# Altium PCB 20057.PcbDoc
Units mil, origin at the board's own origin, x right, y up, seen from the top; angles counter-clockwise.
Board outline 3410.03 x 2160.03 mil, 4 copper layers (Top Layer, Internal Plane 1, Internal Plane 2, Bottom Layer), stack 61.88 mil thick; 85 components, 49 nets, 375 pads, 184 vias.
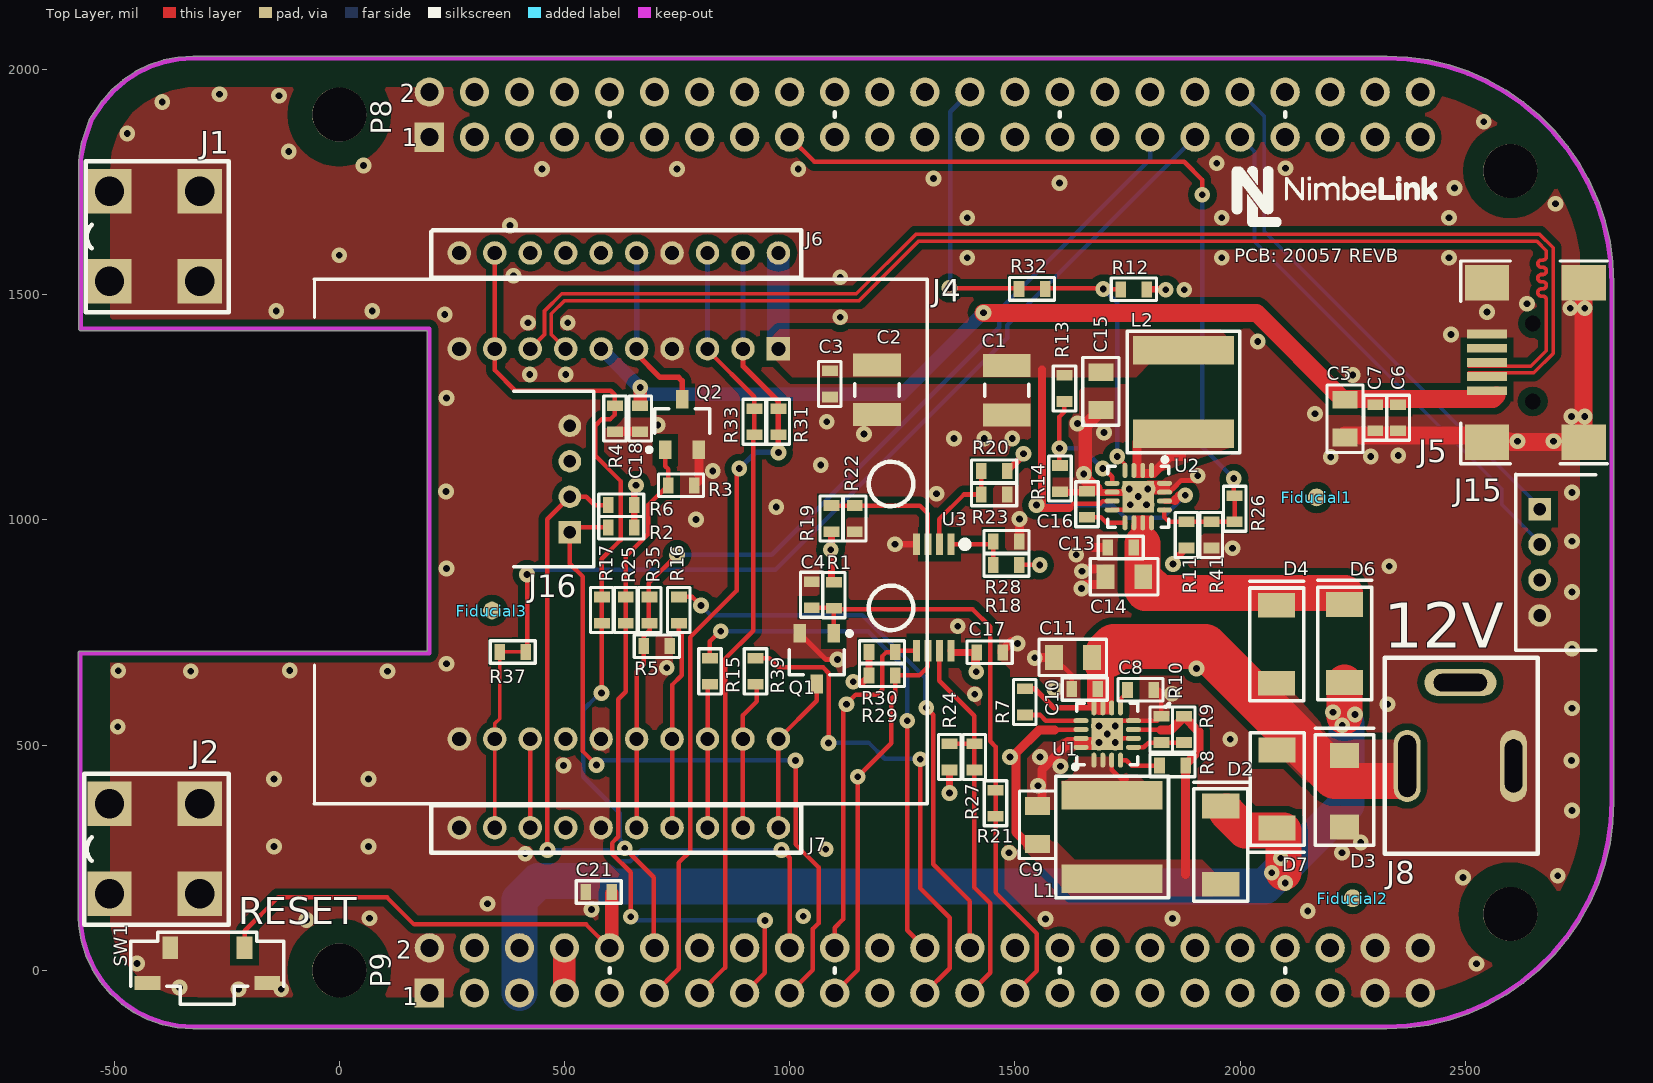
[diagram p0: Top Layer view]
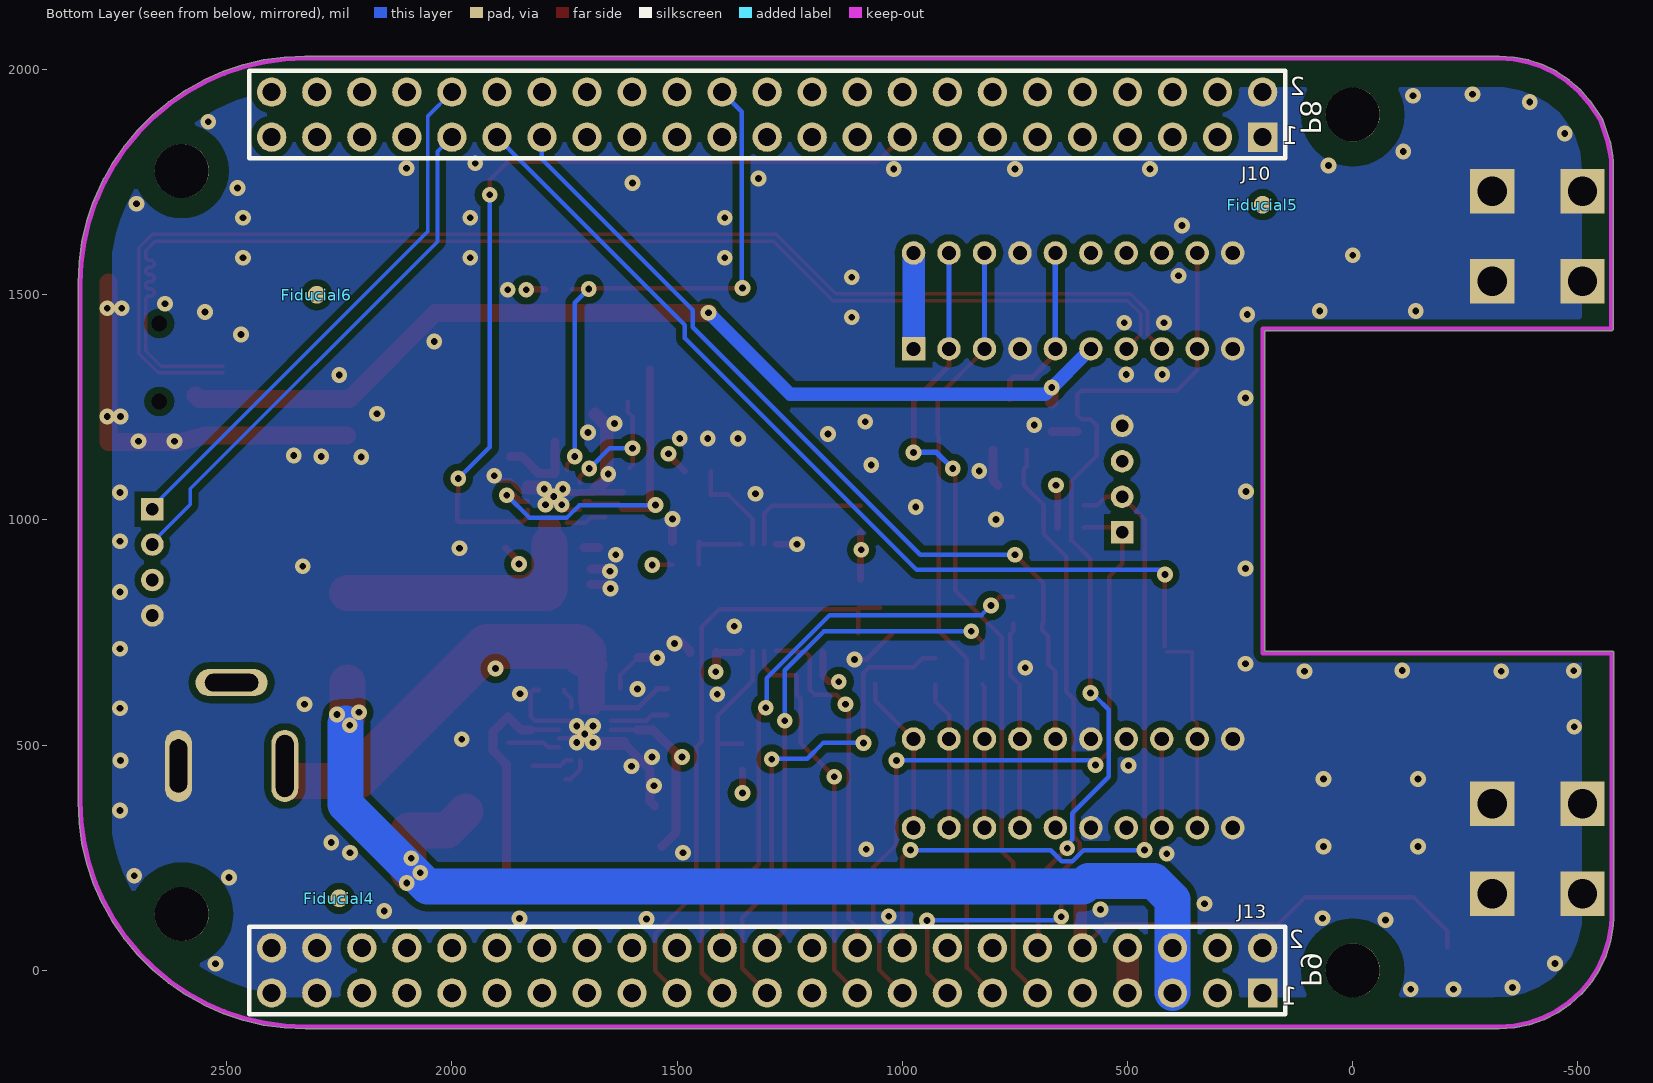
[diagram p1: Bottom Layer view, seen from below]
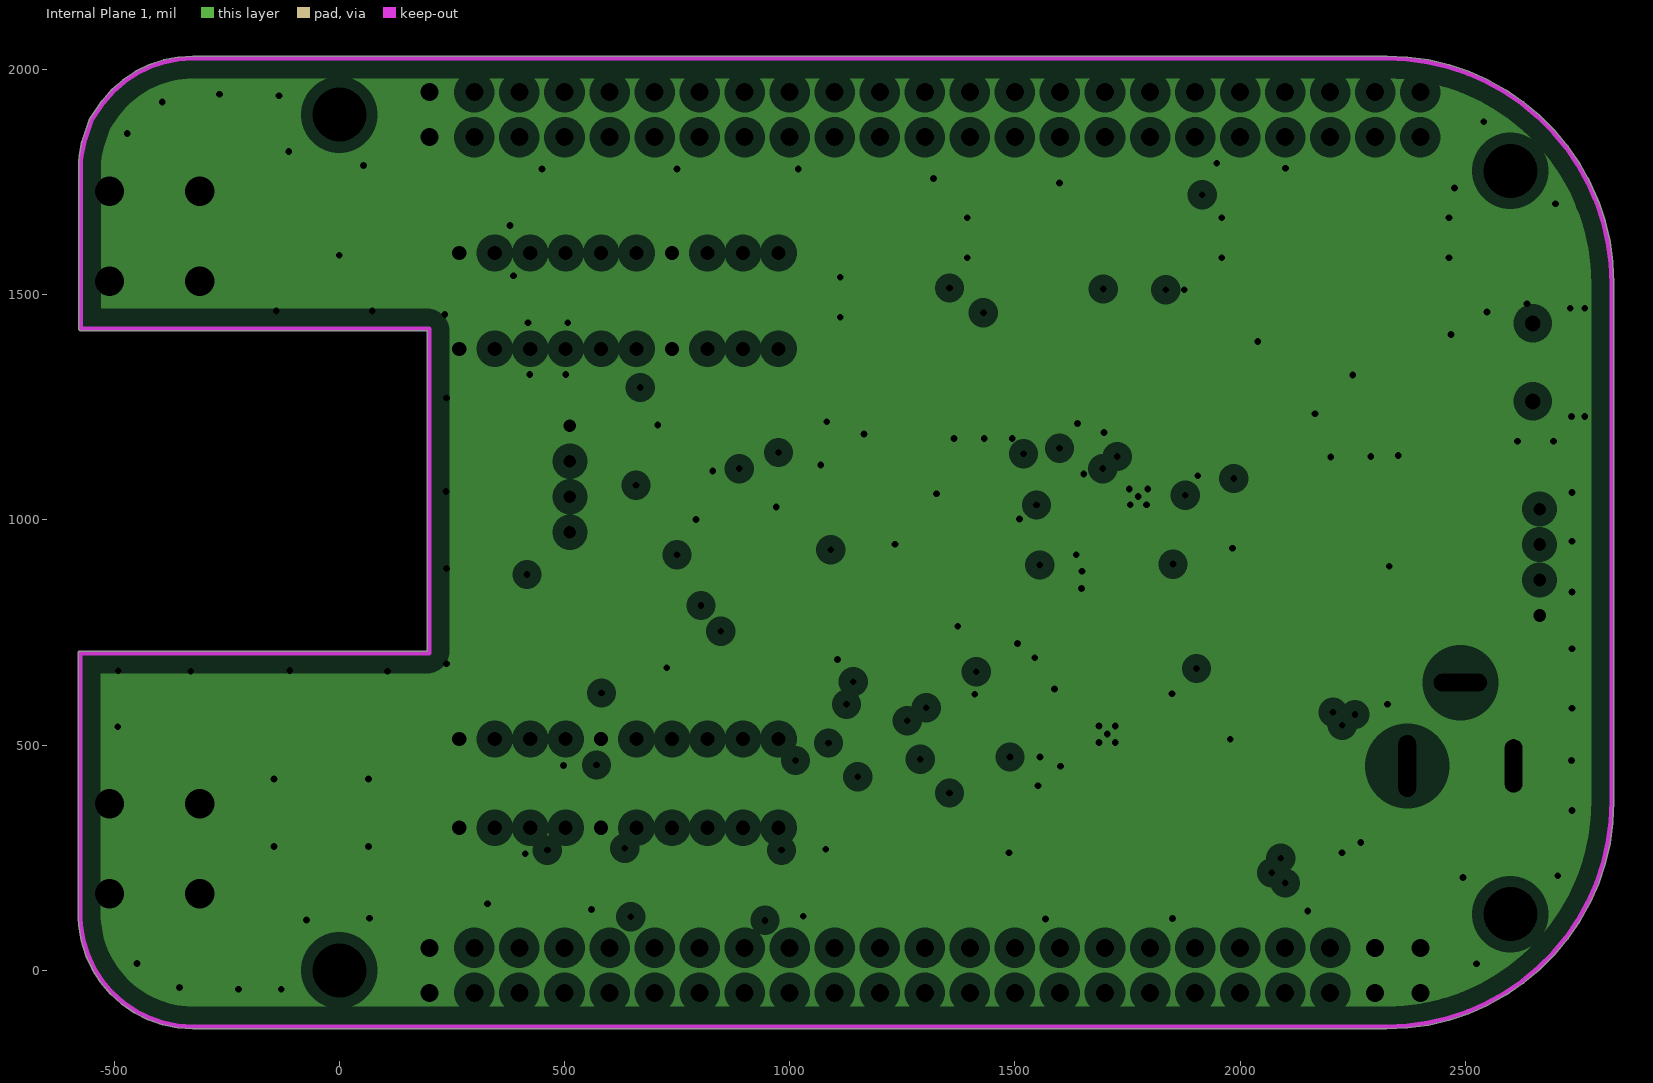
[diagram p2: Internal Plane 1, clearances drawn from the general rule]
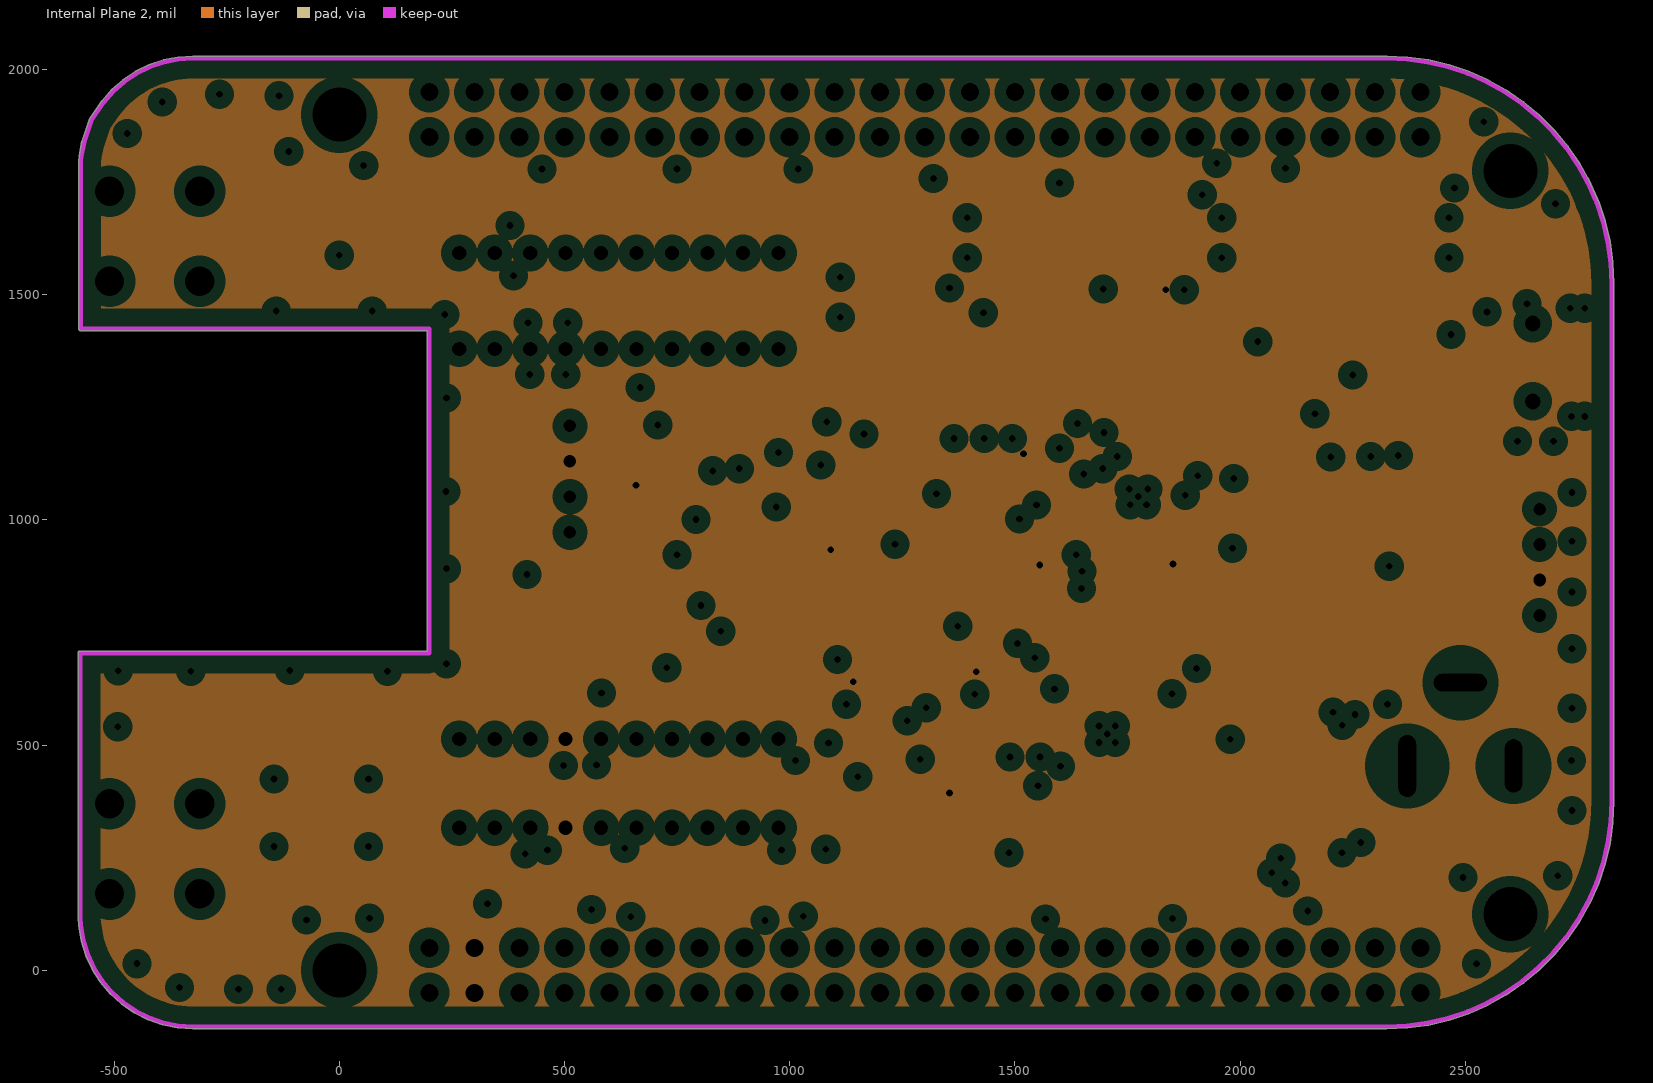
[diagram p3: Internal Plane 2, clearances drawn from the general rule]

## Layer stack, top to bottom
Top Solder: solder mask 0.4, Solder Resist, Dk 3.5
Top Layer: signal copper 1.37
Dielectric 1: core 6.7, FR-4, Dk 4.6
Internal Plane 1: plane copper 1.37, net GND
Dielectric 3: prepreg 43, Dk 4.2
Internal Plane 2: plane copper 1.37, net VCC_3V3
Dielectric 2: core 6.7, Dk 4.2
Bottom Layer: signal copper 1.37
Bottom Solder: solder mask 0.4, Solder Resist, Dk 3.5

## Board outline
-562.85,33.06 cw(c-558.3,35.17) -563.09,33.68 -572.98,65.58 cw(c-568.19,67.07) -573.14,66.25 -578.69,99.15 cw(c-573.75,100) -578.75,99.64 -579.97,116.76 cw(c-574.96,117.11) -579.98,117.11 -580.02,165 cw(c-575,165) -580.02,165 -580.02,328.93 -580.02,445 cw(c-575,445) -580.01,445.06 -580.01,445 ccw(c-575,445) -580.01,445 -580.01,445.06 -580.01,703.84 cw(c-575,703.84) -575,708.86 194.99,708.86 194.98,1419.99 -573.59,1419.98 cw(c-573.59,1425) -578.61,1425 -578.61,1796.44 cw(c-573.59,1796.44) -578.6,1796.77 -577.87,1807.96 cw(c-572.86,1807.63) -577.78,1808.63 -571.4,1840.67 cw(c-566.48,1839.71) -571.23,1841.32 -571.22,1841.34 -555.42,1887.88 cw(c-550.67,1886.29) -554.84,1889.08 -554.83,1889.08 -527.51,1929.97 -527.5,1929.98 ccw(c-523.34,1927.19) -527.51,1929.97 -527.51,1929.98 cw(c-523.34,1927.19) -527.11,1930.5 -505.55,1955.08 cw(c-501.78,1951.78) -505.08,1955.55 -480.5,1977.11 cw(c-477.19,1973.34) -479.98,1977.51 -479.97,1977.51 -452.79,1995.67 cw(c-450,1991.51) -452.78,1995.68 -452.79,1995.68 cw(c-450,1991.51) -452.2,1996.01 -422.91,2010.46 cw(c-420.67,2005.97) -422.28,2010.72 -422.27,2010.72 -391.33,2021.23 cw(c-389.7,2016.48) -390.68,2021.4 -358.61,2027.78 cw(c-357.63,2022.86) -357.96,2027.87 -325.33,2030 cw(c-325,2025) -325,2030.02 2325,2030.02 cw(c2325,2025) 2325.25,2030.01 2371.34,2027.88 cw(c2371.13,2022.87) 2371.83,2027.83 2371.82,2027.83 cw(c2371.13,2022.87) 2371.83,2027.83 2417.56,2021.45 cw(c2416.87,2016.49) 2417.57,2021.45 2417.56,2021.45 2417.57,2021.45 cw(c2416.87,2016.49) 2418.02,2021.37 2462.98,2010.79 cw(c2461.83,2005.91) 2463.44,2010.66 2463.43,2010.67 2463.44,2010.66 2507.2,1996 2507.21,1995.99 2507.2,1996 cw(c2505.62,1991.24) 2507.65,1995.82 2549.89,1977.17 cw(c2547.87,1972.58) 2550.32,1976.96 2590.64,1954.5 cw(c2588.22,1950.11) 2591.05,1954.25 2591.06,1954.24 ccw(c2588.22,1950.11) 2590.66,1954.49 2590.64,1954.5 2591.06,1954.24 2629.14,1928.16 2629.15,1928.15 cw(c2626.32,1924.01) 2629.53,1927.86 2665.04,1898.37 2665.05,1898.36 cw(c2661.85,1894.5) 2665.41,1898.03 2665.39,1898.05 2698.05,1865.39 cw(c2694.5,1861.85) 2698.37,1865.04 2727.86,1829.53 cw(c2724.01,1826.32) 2728.15,1829.15 2728.16,1829.14 2754.24,1791.06 2754.25,1791.05 cw(c2750.11,1788.22) 2754.5,1790.64 2754.49,1790.66 ccw(c2750.11,1788.22) 2754.24,1791.06 2754.5,1790.64 2772.43,1758.45 cw(c2769.9,1754.12) 2774.49,1756.15 2793.14,1713.9 cw(c2788.56,1711.87) 2793.57,1711.87 cw(c2788.56,1711.87) 2793.28,1710.2 cw(c2791.24,1705.62) 2795.99,1707.21 2810.66,1663.44 2810.67,1663.43 2810.66,1663.44 cw(c2805.91,1661.83) 2810.79,1662.98 2821.37,1618.02 cw(c2816.49,1616.87) 2821.45,1617.57 2821.45,1617.56 2827.83,1571.83 cw(c2822.87,1571.13) 2827.83,1571.82 2827.83,1571.83 cw(c2822.87,1571.13) 2827.88,1571.34 2827.88,1571.37 2827.88,1571.34 2830.01,1525.25 cw(c2825,1525) 2830.02,1525 2830.02,375 cw(c2825,375) 2830.01,374.75 2830.01,374.77 2830.01,374.75 2827.88,328.66 2827.88,328.63 2827.88,328.66 cw(c2822.87,328.87) 2827.83,328.17 2827.83,328.18 cw(c2822.87,328.87) 2827.83,328.17 2827.83,328.18 2827.83,328.17 2821.45,282.44 2821.45,282.43 ccw(c2816.49,283.13) 2821.45,282.44 2821.45,282.43 cw(c2816.49,283.13) 2821.37,281.98 2810.79,237.02 cw(c2805.91,238.17) 2810.66,236.56 2810.67,236.57 2810.66,236.56 2796,192.8 2795.99,192.79 2796,192.8 cw(c2791.24,194.38) 2795.82,192.35 2777.17,150.11 cw(c2772.58,152.13) 2776.96,149.68 2776.96,149.69 2776.96,149.68 2754.5,109.36 cw(c2750.11,111.78) 2754.25,108.95 2728.15,70.85 cw(c2724.01,73.68) 2727.86,70.47 2727.87,70.48 2727.86,70.47 2698.37,34.96 2698.36,34.95 2698.37,34.96 cw(c2694.5,38.15) 2698.05,34.61 2665.39,1.95 cw(c2661.85,5.5) 2665.04,1.63 2665.05,1.64 2665.04,1.63 2629.53,-27.86 2629.52,-27.87 cw(c2626.32,-24.01) 2629.14,-28.16 2629.15,-28.15 ccw(c2626.32,-24.01) 2629.53,-27.86 2629.14,-28.16 2591.06,-54.24 2591.05,-54.25 cw(c2588.22,-50.11) 2590.64,-54.5 2590.66,-54.49 ccw(c2588.22,-50.11) 2591.06,-54.24 2590.64,-54.5 2550.32,-76.96 2550.31,-76.96 2550.32,-76.96 cw(c2547.87,-72.58) 2549.89,-77.17 2507.65,-95.82 cw(c2505.62,-91.24) 2507.2,-96 2507.21,-95.99 2507.2,-96 2463.44,-110.66 cw(c2461.83,-105.91) 2462.98,-110.79 2418.02,-121.37 cw(c2416.87,-116.49) 2417.55,-121.46 2417.57,-121.45 2417.55,-121.46 2371.84,-127.83 2371.83,-127.83 cw(c2371.13,-122.87) 2371.34,-127.88 2371.37,-127.88 ccw(c2371.13,-122.87) 2371.84,-127.83 2371.34,-127.88 2325.25,-130.01 2325.23,-130.01 2325.25,-130.01 cw(c2325,-125) 2325,-130.01 -325,-130.01 cw(c-325,-125) -325.34,-130 -358.66,-127.77 cw(c-358.32,-122.77) -359.32,-127.68 -392.05,-121.03 cw(c-391.05,-116.12) -392.7,-120.85 -424.25,-109.9 cw(c-422.6,-105.16) -424.87,-109.64 -454.67,-94.57 cw(c-452.41,-90.1) -455.25,-94.23 -482.78,-75.33 cw(c-479.95,-71.19) -483.31,-74.91 -508.08,-52.51 cw(c-504.72,-48.79) -508.54,-52.03 cw(c-504.72,-48.79) -508.55,-52.02 -530.1,-26.52 -530.11,-26.52 cw(c-526.28,-23.28) -530.5,-25.98 -548.47,2.17 cw(c-544.25,4.87) -548.8,2.76

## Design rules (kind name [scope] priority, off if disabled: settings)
Clearance Clearance_1 [InPolygon] p1: gap=15
Clearance [All] p2: gap=6
ComponentClearance [All] p1: gap=7 collisioncheckmode=3 verticalgap=7 showdistances=FALSE
DiffPairsRouting [All] p1: maxlimit=30 minlimit=7 mostfreqgap=7 toplayer_minwidth=7 toplayer_maxwidth=100 toplayer_prefwidth=8 bottomlayer_minwidth=7 bottomlayer_maxwidth=100 bottomlayer_prefwidth=8 maxuncoupledlength=500
HoleSize [All] p1: absolutevalues=TRUE maxlimit=500 minlimit=15 maxpercent=80.000 minpercent=20.000
MinimumAnnularRing [All] p1: minimumring=10
MinimumSolderMaskSliver [All] p1: minsoldermaskwidth=0
PlaneClearance [All] p1: clearance=25
PlaneConnect [All] p1: planeconnectstyle=Direct reliefexpansion=20 reliefentries=4 reliefconductorwidth=20 reliefairgap=15
PolygonConnect "All Rule" [All] p1: connectstyle=Direct reliefconductorwidth=10 reliefentries=4 polygonreliefangle="90 Angle" airgapwidth=10
RoutingVias [All] p1: holewidth=15 width=35 viastyle="Through Hole" minholewidth=15 minwidth=35 maxholewidth=300 maxwidth=500
ShortCircuit ShortCircuit_1 [(InComponent('J9') OR InComponent('J10') OR InComponent('J11') OR InComponent('J12') OR InComponent('J13') OR InComponent('J14')) vs (InComponent('J9') OR InComponent('J10') OR InComponent('J11') OR InComponent('J12') OR InComponent('J13') OR InComponent('J14'))] p1 off: allowed=TRUE
ShortCircuit [All] p2: allowed=FALSE
SilkToSilkClearance [All] p1: silktosilkclearance=0
SilkToSolderMaskClearance [IsPad] p1: minsilkscreentomaskgap=0 clearancetoexposedcopper=TRUE
SolderMaskExpansion SolderMaskExpansion_2 [isVia and TestpointBottom] p1: expansion=0
SolderMaskExpansion SolderMaskExpansion_1 [IsVia] p2: expansion=-10
SolderMaskExpansion [All] p3: expansion=0
UnpouredPolygon [All] p1: allowunpoured=FALSE
Width [All] p1: maxlimit=5000 minlimit=7 preferedwidth=10
20 further rules are at their usual default settings.

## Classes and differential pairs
component class Skywire: C1 C2 C3 C4 C5 C6 C7 C18 J1 J2 J4 J5 J6 J7 Q1 Q2 R1 R3 R4 R5
net class DIFF90: SKY_USB_N SKY_USB_P
component class Power: C8 C9 C10 C11 C13 C14 C15 C16 D2 D3 D4 D6 D7 J8 L1 L2 R7 R8 R9 R10 R11 R12 R13 R14 R41 U1 U2
component class TOP: C17 C21 Fiducial1 Fiducial2 Fiducial3 Fiducial4 Fiducial5 Fiducial6 J10 J13 J15 J16 R2 R6 R15 R16 R17 R18 R19 R20 R21 R22 R23 R24 R25 R26 R27 R28 R29 R30 R31 R32 R33 R35 R37 R39 SW1 U3
differential pair SKY_USB: +SKY_USB_P -SKY_USB_N

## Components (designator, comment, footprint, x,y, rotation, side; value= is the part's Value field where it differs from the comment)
C1 "LMK325BJ107MM-T" CAPC3225X25N_1210 1482,1288 r270 top
C2 "LMK325BJ107MM-T" CAPC3225X25N_1210 1194,1289 r270 top
C3 "C, 0.1 uF, 16V, 5%, X7R, 0603 CER" 0603 1089,1302 r270 top
C4 "C, 0.1 uF, 16V, 5%, X7R, 0603 CER" 0603 1049,834 r90 top
C5 "C, 10 uF, 25V, 10% ,X5R, 0805 CER" 0805 2233,1216 r270 top
C6 "C, 0.1 uF, 16V, 5%, X7R, 0603 CER" 0603 2351,1227 r270 top
C7 "C, 10 nF, 25V, 10%, X7R, 0603 CER" 0603 2300,1227 r270 top
C8 "C, 470 pF, 50V, NP0, 0603 CER_1" 0603 1779,623 r180 top
C9 "22uF" 0805 1550,332 r90 top
C10 "C, 0.1 uF, 16V, 5%, X7R, 0603 CER" 0603 1654.99,624.84 r180 top
C11 "C, 10 uF, 25V, 10% ,X5R, 0805 CER" 0805 1619.99,694.84 r180 top
C13 "C, 0.1 uF, 16V, 5%, X7R, 0603 CER" 0603 1734.99,938.84 r180 top
C14 "C, 10 uF, 25V, 10% ,X5R, 0805 CER" 0805 1733.99,873.84 r180 top
C15 "22uF" 0805 1691,1277 r270 top
C16 "C, 470 pF, 50V, NP0, 0603 CER_1" 0603 1660,1035 r270 top
C17 "C, 0.1 uF, 16V, 5%, X7R, 0603 CER" 0603 1444,706 r0 top
C18 "C, 0.1 uF, 16V, 5%, X7R, 0603 CER" 0603 668,1225 r270 top
C21 "C, 0.1 uF, 16V, 5%, X7R, 0603 CER" 0603 576,174 r180 top
D2 "PMEG3030EP,115" SOD128 1957,278 r90 top
D3 "SMAJ17A" "DO-214AC, SMA" 2232,398 r90 top
D4 "PMEG3030EP,115" SOD128 2081,724 r90 top
D6 "PMEG3030EP,115" SOD128 2232,726 r90 top
D7 "PMEG3030EP,115" SOD128 2082.12,402.72 r270 top
Fiducial1 "Fiducial" "Fiducial 1mm"#1 2170,1047 r90 top
Fiducial2 "Fiducial" "Fiducial 1mm"#2 2261,162 r90 top
Fiducial3 "Fiducial" "Fiducial 1mm"#3 338,802 r90 top
Fiducial4 "Fiducial" "Fiducial 1mm"#4 2263,158 r90 bottom
Fiducial5 "Fiducial" "Fiducial 1mm"#5 196,1715 r90 bottom
Fiducial6 "Fiducial" "Fiducial 1mm"#6 2310,1497 r90 bottom
J1 "UFL to SMA" "UFL TO SMA" -510,1729.84 r270 top locked
J2 "UFL to SMA" "UFL TO SMA" -510,369.84 r270 top locked
J4 "SKYWIRE SOCKET TH" "SKYWIRE SOCKET" 975,1379.84 r270 top locked
J5 "USB MINI B" 10033526-N3212LF 2880,1349.84 r90 top
J6 "NPPN101BFCN-RC" "Socket 2mm 1x10 NP" 975,1592.84 r270 top
J7 "NPPN101BFCN-RC" "Socket 2mm 1x10 NP" 975,316.84 r270 top
J8 "PJ-202A" PJ-202A 2371,453.84 r0 top
J10 "PRPC023DFAN-RC" PRPC023DFAN-RC 200,1850 r90 bottom
J13 "PRPC023DFAN-RC" PRPC023DFAN-RC 200,-50 r90 bottom
J15 "S4B-PH-K-S(LF)(SN)" S4B-PH-K-S(LF)(SN) 2665,788 r270 top
J16 "S4B-PH-K-S(LF)(SN)" S4B-PH-K-S(LF)(SN) 512,1209 r90 top
L1 "NR6028T2R2N" NR6028 1716,296 r270 top
L2 "NR6028T2R2N" NR6028 1874,1284 r90 top
Q1 "FDV301N" SOT95P300X115-3N 1060,692 r270 top
Q2 "FDV301N" SOT95P300X115-3N 761,1212 r90 top
R1 "100K" 0603 1098,833 r90 top
R2 "R, 4.7K, 1%, 1/10W, 0603" 0603 626,983 r0 top
R3 "10K" 0603 759,1077 r180 top
R4 "#NAME?" 0603 612,1225 r90 top
R5 "#NAME?" 0603 705,720 r180 top
R6 "R, 4.7K, 1%, 1/10W, 0603" 0603 625.99,1032.84 r0 top
R7 "100K" 0603 1522,596 r90 top
R8 "100K" 0603 1849.99,454.84 r0 top
R9 "R, 953K, 1%, 1/10W, 0603" 0603 1874.99,534.84 r90 top
R10 "R, 180K, 1%, 1/10W, 0603" 0603 1824.99,534.84 r270 top
R11 "100K" 0603 1880.99,966.84 r270 top
R12 "100K" 0603 1764,1512 r0 top
R13 "715K" 0603 1610,1292 r90 top
R14 "R, 180K, 1%, 1/10W, 0603" 0603 1600,1092 r90 top
R15 "0" 0603 823,664 r90 top
R16 "0" 0603 754,800 r90 top
R17 "0" 0603 583,800 r90 top
R18 "10K" 0603 1481.01,900.16 r0 top
R19 "10K" 0603 1092.59,1002.99 r270 top
R20 "10K" 0603 1454.01,1108.41 r0 top
R21 "0" 0603 1457,371 r90 top
R22 "10K" 0603 1144.44,1002.99 r90 top
R23 "10K" 0603 1454.01,1056.56 r180 top
R24 "10K" 0603 1355,474 r270 top
R25 "0" 0603 636,800 r90 top
R26 "0" 0603 1988,1024.84 r270 top
R27 "0" 0603 1409.99,473.84 r90 top
R28 "10K" 0603 1481.01,952.01 r180 top
R29 "R, 4.7K, 1%, 1/10W, 0603" 0603 1205,655 r180 top
R30 "R, 4.7K, 1%, 1/10W, 0603" 0603 1204.99,706.84 r180 top
R31 "0" 0603 974.83,1218 r270 top
R32 "0" 0603 1538,1513 r180 top
R33 "0" 0603 921.66,1218 r270 top
R35 "0" 0603 689,800 r90 top
R37 "0" 0603 385,707 r0 top
R39 "0" 0603 924,664 r90 top
R41 "100K" 0603 1936,966.84 r90 top
SW1 "TL3330AF260QG" TL3330AF260QG -294,5 r180 top
U1 "TPS62130" QFN50P300X300X100_HS-17N 1704.99,524.84 r90 top
U2 "TPS62130" QFN50P300X300X100_HS-17N 1773.99,1051.84 r270 top
U3 "CAT24C256YI-GT3" "TSSOP8 4.4x3 CASE 948AL-01" 1357.99,945.84 r270 top

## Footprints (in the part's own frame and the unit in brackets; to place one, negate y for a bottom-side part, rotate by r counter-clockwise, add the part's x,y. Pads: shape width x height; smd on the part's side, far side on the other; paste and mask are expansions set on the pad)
0603 [mm]
  rect 0.6x0.9 smd: 1(-0.737,0) 2(0.737,0)
  silkscreen extent -1.27,-0.64 1.27,0.64, body extent -0.8,-0.38 0.8,0.42, height 0.45
0805 [mm]
  rect 1x1.4 smd: 1(-1.3,0) 2(0.838,0)
  silkscreen extent -2.12,-1.03 1.69,1.02, body extent -1.21,-0.6 0.79,0.65, height 0.5
10033526-N3212LF [mm]
  rect 0x0 hole 0.9 unplated: 0(-2.2,5.85) 0(2.2,5.85)
  rect 0.5x2.25 smd: 1(-1.6,8.43) 2(-0.8,8.43) 3(0,8.43) 4(0.8,8.43) 5(1.6,8.43)
  rect 2x2.5 smd: 6(-4.5,8.43) 6(-4.5,2.98) 6(4.5,8.43) 6(4.5,2.98)
  silkscreen extent -5.72,1.65 5.71,9.91, body extent -4.95,0 4.95,9.4, height 4.05
CAPC3225X25N_1210 [mm] "Chip Capacitor, 2-Leads, 1210"
  rect 1.3x2.7 smd: 1(-1.4,0) 2(1.4,0)
  silkscreen extent -0.35,-1.25 0.35,1.25, body extent -1.7,-1.35 1.7,1.35, height 2.5
"DO-214AC, SMA" [mm]
  rect 1.4x1.64 smd: A(-2.015,0) K(2.015,0)
  silkscreen extent -3.05,-1.65 3.56,1.65, body extent -2.35,-1.46 2.35,1.46, height 2.5
"Fiducial 1mm"#1 [mm]
  round 1 smd paste-0.5: Fiducial(0.076,0)
"Fiducial 1mm"#2 [mm]
  round 1 smd paste-0.5: Fiducial(-0.051,0.279)
"Fiducial 1mm"#3 [mm]
  round 1 smd paste-0.5: Fiducial(-0.076,-0.025)
"Fiducial 1mm"#4 [mm]
  round 1 smd paste-0.5: Fiducial(0.051,-0.33)
"Fiducial 1mm"#5 [mm]
  round 1 smd paste-0.5: Fiducial(-0.381,0.102)
"Fiducial 1mm"#6 [mm]
  round 1 smd paste-0.5: Fiducial(0.076,-0.254)
NR6028 [mm]
  rect 1.6x5.7 smd: 1(-2.35,0) 2(2.35,0)
  silkscreen extent -3.43,-3.18 3.43,3.18, body extent -3.05,-3.05 3.05,3.05, height 2.8
PJ-202A [mil] "PJ-202A  Barrel Plug"
  oval 60x160 hole 39.37 slot 137.8 at 90 deg: 1(0,0)
  oval 160x60 hole 39.37 slot 118.11 at 0 deg: 2(118.11,185.04)
  oval 60x160 hole 39.37 slot 118.11 at 90 deg: 3(236.22,0)
  silkscreen extent -50,-195 290,240, body extent -28,-180 538,190, height 433
PRPC023DFAN-RC [mil]
  rect 65x65 hole 40: 1(0,0)
  round 65 hole 40: 2(100,0) 3(0,100) 4(100,100) 5(0,200) 6(100,200) 7(0,300) 8(100,300) 9(0,400) 10(100,400) 11(0,500) 12(100,500) 13(0,600) 14(100,600) 15(0,700) 16(100,700) 17(0,800) 18(100,800) 19(0,900) 20(100,900) 21(0,1000) 22(100,1000) 23(0,1100) 24(100,1100) 25(0,1200) 26(100,1200) 27(0,1300) 28(100,1300) 29(0,1400) 30(100,1400) 31(0,1500) 32(100,1500) 33(0,1600) 34(100,1600) 35(0,1700) 36(100,1700) 37(0,1800) 38(100,1800) 39(0,1900) 40(100,1900) 41(0,2000) 42(100,2000) 43(0,2100) 44(100,2100) 45(0,2200) 46(100,2200)
  silkscreen extent -47,-50 147,2250, body extent -49,-51 148,2249, height 417
QFN50P300X300X100_HS-17N [mm] "QFN, 16-Leads, Body 3.00x3.00mm, Pitch 0.50mm, Thermal Pad 1.78x1.78mm, IPC Medium Density"
  oval 0.85x0.28 smd: 1(-1.475,0.75) 2(-1.475,0.25) 3(-1.475,-0.25) 4(-1.475,-0.75) 9(1.475,-0.75) 10(1.475,-0.25) 11(1.475,0.25) 12(1.475,0.75)
  oval 0.28x0.85 smd: 5(-0.75,-1.475) 6(-0.25,-1.475) 7(0.25,-1.475) 8(0.75,-1.475) 13(0.75,1.475) 14(0.25,1.475) 15(-0.25,1.475) 16(-0.75,1.475)
  rect 1.78x1.78 smd paste-0.8: 17(0,0)
  silkscreen extent -1.98,-1.73 1.73,1.93, body extent -1.58,-1.57 1.57,1.58, height 1
S4B-PH-K-S(LF)(SN) [mil]
  rect 50x50 hole 28: 1(-236.22,0)
  round 50 hole 28: 2(-157.48,0) 3(-78.74,0) 4(0,0)
  silkscreen extent -313,-53 77,125, body extent -313,-53 77,246, height 189
"SKYWIRE SOCKET" [mm]
  rect 1.321x1.321 hole 0.8: 1(0,0)
  round 1.321 hole 0.8: 2(0,-2) 3(0,-4) 4(0,-6) 5(0,-8) 6(0,-10) 7(0,-12) 8(0,-14) 9(0,-16) 10(0,-18) 11(22,-18) 12(22,-16) 13(22,-14) 14(22,-12) 15(22,-10) 16(22,-8) 17(22,-6) 18(22,-4) 19(22,-2) 20(22,0)
  silkscreen extent -3.94,-26.16 25.65,8.38, body extent -3.57,-25.75 25.38,8.13, height 10.92
"Socket 2mm 1x10 NP" [mil]
  round 52 hole 31.5: 1(0,0) 2(0,-78.74) 3(0,-157.48) 4(0,-236.22) 5(0,-314.96) 6(0,-393.7) 7(0,-472.44) 8(0,-551.18) 9(0,-629.92) 10(0,-708.66)
  silkscreen extent -50,-771 55,50
SOD128 [mm]
  rect 1.4x2.1 smd: A(-2.2,0) K(2.2,0)
  silkscreen extent -3.17,-1.52 3.56,1.52, body extent -2.03,-1.33 1.91,1.4, height 2.5
SOT95P300X115-3N [mm] "SOT23, 3-Leads, Body 3.10x3.00mm, Pitch 0.95mm, IPC Medium Density"
  rect 1.05x0.7 smd: 1(-1.425,0.95) 2(-1.425,-0.95) 3(1.425,0)
  silkscreen extent -1.55,-1.55 0.9,1.98, body extent -0.9,-1.55 0.9,1.55, height 1.15
TL3330AF260QG [mil] "RA SPST-NO Momentary"
  rect 35x50 smd: 1(81.5,-45) 2(-83.5,-45)
  rect 57x31 smd: 3(-134,33) 3(132,33)
  silkscreen extent -171,-80 169,80, body extent -154,-63 154,80, height 138
"TSSOP8 4.4x3 CASE 948AL-01" [mm]
  rect 1.2x0.4 smd: 1(0,0) 2(0,-0.65) 3(0,-1.3) 4(0,-1.95) 5(6,-1.95) 6(6,-1.3) 7(6,-0.65) 8(6,0)
  silkscreen extent -0.05,0.74 0.05,0.84, body extent -0.35,-2.46 6.25,0.59, height 1.2
"UFL TO SMA" [mm]
  rect 2.5x2.5 hole 1.651: 1(0,5.08) 1(0,0) 1(5.08,5.08) 1(5.08,0)
  silkscreen extent -1.7,-1.35 6.81,6.73, body extent -1.02,-10.03 5.97,22.61, height 9.44

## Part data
C1 C2: "C, 100 uF, 10V, 20%, X5R, 1210 CER"
C8 C16: "C, 470 pF, 50V, NP0, 0603 CER"
C9 C15: library part "CAP 22uF 10V 20% X5R 0805 CER", "Cap 22uF 10V 20% X5R 0805 CER"
D2 D4 D6 D7: "D, SCHOTTKY, 30V, 0.360VF, 3A, SOD-128"
D3: "D, TVS, UNIDIRECTIONAL, 17V, 14.5A, SMA"
Fiducial1 Fiducial2 Fiducial3 Fiducial4 Fiducial5 Fiducial6: "Fiducial, 1mm"
J1 J2: library part RFSMARA-7053-DOWN, "J, ANT, UFL to SMA, TH"
J4: "J, Cellular, Nimbelink, Skywire, 3.6V-4.2V, Through Hole XBEE"
J5: library part 10033526-N3212LF, "J, USB, MINI B, RIGHT ANGLE, SMD"
J6 J7: "J, HEADER, FEMALE, 2.00mm, 10x1, TH"
J8: "J, Barrel, 2.1mm ID, 5.5mm OD"
J10 J13: "J, HEADER, MALE, 2.54mm, 23x2, 8.08mm,TH"
J15 J16: "J, HEADER, MALE, RA, 2.00mm, 4x1, TH"
L1 L2: "L, 2.2uH, 3.7A, 26 mOHM, 30%, 6x6x2.8mm"
Q1 Q2: "Q, MOSFET, N-CH, 25V, 0.220mA, SOT-23-3"
R1 R7 R8 R11 R12 R41: library part "R, 100K, 1%, 1/10W, 0603", "R, 100K, 1%, 1/10W, 0603"
R3 R18 R19 R20 R22 R23 R24 R28: library part "R, 10K, 1%, 1/10W, 0603", "R, 10K, 1%, 1/10W, 0603"
R4 R5: library part "R, 1K, 1%, 1/10W, 0603", "R, 1K, 1%, 1/10W, 0603"
R13: library part "R, 715K, 1%, .1W, 0603", "R, 715K, 1%, .1W, 0603"
R15 R16 R17 R21 R25 R26 R27 R31 R32 R33 R35 R37 R39: library part "R, 0, 1/10W, 0603", "R, 0, 1/10W, 0603"
SW1: "SW, SPST-NO, 12V, 0.05A, 6.90x3.40mm, SMD, RIGHT ANGLE"
U1 U2: "U, DC/DC BUCK, 3V-17V , 3A, QFN"
U3: "U, EEPROM, I2C, 256KB, 400kHz, 1.8V-5.5V, TSSOP8"

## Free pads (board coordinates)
  round 200 on Keep-Out: 0(0,0) 1(0,1900) 2(2600,125)
  round 10 on Mech1: 0(200,1850) 1(200,1950) 2(300,1950) 2(400,1950) 2(500,1950) 2(600,1950) 2(1500,-50) 2(1500,50) 2(1600,-50) 2(1600,50) 3(300,1850) 4(2400,1850) 5(2400,1950) 6(2300,1950) 7(2300,1850) 8(2400,50) 9(2300,50) 10(2300,-50) 11(2400,-50) 12(200,-50) 13(300,-50) 14(300,50) 15(200,50)
  round 120 hole 120: 1(0,0) 1(0,1900) 1(2600,125) 1(2600,1775)
  round 180 on Keep-Out: 2(2600,1775)

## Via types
v1: diameter 35, hole 15, Top Layer to Bottom Layer, 184 vias

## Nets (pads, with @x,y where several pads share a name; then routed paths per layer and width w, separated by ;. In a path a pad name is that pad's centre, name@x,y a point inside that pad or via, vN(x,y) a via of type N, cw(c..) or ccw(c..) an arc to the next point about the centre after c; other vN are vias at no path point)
GND: C1.2 C2.2 C3.2 C4.2 C5.2 C6.2 C7.2 C8.1 C9.2 C10.2 C11.2 C13.2 C14.2 C15.2 C16.1 C17.2 C18.2 C21.2 D3.A J1.1 J2.1 J4.4 J4.10 J4.11 J4.15 J5.5 J5.6 J6.4 J6.10 J7.6 J7.10 J8.3 J10.1 J10.2 J13.1 J13.2 J13.43 J13.44 J13.45 J13.46 J15.4 J16.4 Q1.2 Q2.2 R3.1 R4.1 R5.1 R10.1 R14.1 R22.1 R23.1 R28.1 R41.1 SW1.1 SW1.3 U1.6 U1.8 U1.15 U1.16 U1.17 U2.6 U2.8 U2.15 U2.16 U2.17 U3.4 | length 2510.6
  Top Layer w10: C11.2 1625.99,655.84 C10.2 ; U2.8 1716.43,1022.83 U2.17@1752.33,1022.83 ; v1(1722.99,542.84) 1734.52,554.37 U1.8 1815.52,554.37 R10.1 1824.99,616.84 ; U1.17@1732.15,515 U1.6
  Top Layer w11: Q1.2 1080.7,690 v1(1106,690) ; C8.1 1818.83,623 1824.99,616.84 1846.16,616.84 v1(1849,614) ; v1@1809.82,1061.69 U2.15 1833.79,1063.41 1845.02,1063.41 1852.67,1071.06 1869.61,1088 v1@1909,1088
  Top Layer w15: v1(1233.99,945.84) U3.4 ; 1620.83,1061.69 1695.99,1061.69 ; 1688.08,1061.01 U2.17@1753.99,1061.01
  Top Layer w20: R4.1 C18.2 ; R3.1 798.4,1087.4 Q2.2 ; C17.2@1470.99,705.84 1470.99,708.99 v1@1492,730 ; R28.1 v1@1510.01,1001.99 ; C9.2 1560,375 1560,445 1618.84,503.84 ; v1@1553.99,694.84 C11.2 ; v1@1657.99,856.84 C14.2@1690.99,856.84 ; v1@1657.99,890.84 C14.2@1690.99,890.84 ; 1673.99,938.84 C13.2@1706.99,938.84 ; U1.17@1684.99,503.84 v1(1686.99,505.84) ; v1(1722.99,505.84) U1.17@1732.15,515
  Top Layer w25: v1(1773.99,1051.84) 1796.83,1074.68 1832.06,1074.68
  Top Layer w28: 1618.84,503.84 U1.17@1684.99,503.84
  Top Layer w30: 1679,1069 1656.5,1091.5 1656.5,1209.5 C15.2@1682,1235
  Top Layer w40: C5.2@2233,1187.68 2547.11,1187.68 2605,1172.68 2762.68,1172.68 J5.6@2762.68,1527.01
  other v1: -224,-42 -129,-42 -355,-38 -449,15 2524.99,14.84 -73,112 1567.84,113.8 1850,115 67,116 1030,120 2150,132 560,135 329,148 2495,206 2705,210 413,259 1487,261 2226,261 1080,269 -145.01,274.84 64.99,274.84 2268,284 2737,354.84 1551,410 -145.01,424.84 64.99,424.84 1601,453 498,455 2736,466 1556,474 1978,513 1704.99,524.84 -492,541 1686.99,542.84 2737,582 2327,591 1411,613 1588,625 -330,664 107,664 -491,665 -110,666 727,672 238,681 1543.99,693.84 2737,714 1506,726 1373,764 2737,840 1648,848 1649,886 238,892 2331,897 1636,923 1983,937 2737,953 792,1001 1510,1002 970,1029 1756.15,1034 1791.99,1033.84 1326,1058 2737,1061 237,1063 1753.99,1068.84 1794.99,1068.84 1906,1098 1653,1102 829,1109 1069,1122 2201,1140 2290,1141 2351,1143 2616,1175 2696,1175 1365,1181 1432,1181 1494,1181 1165,1191 1698,1194 707,1211 1639,1214 1082,1218 2736,1230 2765,1230 2166,1236 238,1271 2250,1322 423,1323 503,1323 2039,1396 2468,1412 419,1438 507,1438 1112,1450 234,1456 2548,1462 -140,1464 73,1464 2733,1470 2765,1470 2637,1480 1876,1511 1112,1539 387,1542 1394,1582 1959,1582 2464,1582 0,1587.59 379,1654 1394,1671 1959,1671 2464,1671 2700,1702 2476,1737 1599,1748 1319,1758 450,1779 750,1779 1019,1779 2101,1781 54,1787 1948,1792 -112,1818 -471,1858 2541,1884 -393,1928 -134,1942 -266,1945
GPIO0_27: J10.17 R11.1 R26.1 R26.2 R41.2 U2.13 | length 1918.1
  Top Layer w10: J10.17@1000.03,1849.89 1054.92,1795 1876,1795 1916,1755 v1(1916,1722) ; U2.13 1832.06,1005.94 1842.16,995.84 R11.1 R41.2 1984.84,995.84 1988,999 R26.1@1988,1057 ; R26.1@1986,1057 v1(1986,1092)
  Bottom Layer w10: v1(1916,1722) 1916,1162 v1(1986,1092)
GPIO1_16: J13.15 Q2.1 R3.2 R25.1 R25.2 | length 1585
  Top Layer w10: v1(647,119) 647,217.7 605.5,259.2 605.5,282.81 619.3,296.6 619.3,602 636,618.7 R25.1 R25.2 636,918.92 686.5,969.42 686.5,1033.5 R3.2 730,1113 723.6,1119.4 Q2.1 ; J13.15@900.03,-50.11 945,-5.15 v1(945,111)
  Bottom Layer w10: v1@648,111 v1(945,111)
GPIO1_17: J13.23 R39.2 | length 1116.8
  Top Layer w10: R39.2@927,693 955,693 975,673 1074,673 1087,660 1087,506 v1(1086,505) ; v1(1290,469) 1290,182 1355,117 1355,4.85 J13.23@1300.03,-50.11
  Bottom Layer w10: v1(1086,505) 1176,505 1211,470 1289,470 v1(1290,469)
GPIO1_28: J4.9 J6.9 J13.12 R4.2 R17.1 R17.2 | length 1925.5
  Top Layer w10: J6.9 J4.9 345.08,1332.92 391,1287 603,1287 612,1278 R4.2 612,1234 602,1224 583,1224 568,1209 568,1143 624.5,1086.5 624.5,955.5 583,914 R17.2 R17.1 583,617 v1(582,616) ; v1(634,271) 698.04,206.96 698.04,51.88 J13.12@700.03,49.89
  Bottom Layer w10: v1@571,616 571,608 542,579 542,430.14 623.04,349.1 623.04,290.56 634,279.6 v1(634,271)
GPIO1_29: J10.26 R12.1 R32.1 R32.2 U2.4 | length 1258.5
  Top Layer w8: v1(1727,1141) 1744.46,1123.54 U2.4
  Top Layer w10: v1(1355,1515) 1694,1515 v1(1696,1513) 1697,1512 R12.1
  Bottom Layer w10: v1(1355,1515) 1357,1517 1357,1830.98 1356.5,1831.48 1356.5,1906.5 J10.26 ; v1(1696,1513) 1727,1482 v1(1727,1141)
GPIO3_19: C4.1 J13.27 Q1.1 R1.1 R21.1 R21.2 | length 1343.5
  Top Layer w10: C4.1 1097,805 R1.1 ; Q1.1 1097.4,802 1406,802 1445,763 1445,508.5 1457,496.5 R21.2 R21.1 1457,173 1549,81 1549,-1.15 J13.27@1500.03,-50.11
GPIO3_21: J13.25 R24.1 R27.1 R27.2 U3.7 | length 880.1
  Top Layer w10: U3.7 1332.4,642.74 1409.99,565.15 R27.2 ; R24.1 1409.83,503 R27.2 ; J13.25@1399.99,-50.16 1445,-5.15 1445,149 1409.99,184.01 R27.1 R27.2
I2C1_SCL: J13.17 J16.1 R2.1 | length 1641.2
  Top Layer w10: v1(571,456) 541,486 541,874 512,903 J16.1 523.22,984 596,984 R2.1 ; J13.17@1000.03,-50.11 1051,0.85 1051,92 1064,105 1064,228.66 1013,279.66 v1(1013,466)
  Bottom Layer w10: v1(571,456) 581,466 v1(1013,466)
I2C1_SDA: J13.18 J16.2 R6.1 | length 1666.3
  Top Layer w10: v1(462,267) 461.82,267.18 461.82,1001.34 J16.2 548.48,1051.52 567.16,1032.84 R6.1 ; v1@976,259 991.03,259 1000.03,250 J13.18@1000.03,49.89
  Bottom Layer w10: v1(462,267) 597.69,267 622.19,242.5 645.8,242.5 670.3,267 v1(982,267)
I2C2_SCL: J13.19 R29.1 U3.6 | length 877.2
  Top Layer w10: J13.19@1099.99,-50.16 1151,0.85 v1(1151,430) 1225.5,504.5 1225.5,602.8 1233.99,611.29 R29.1 1288.15,655 1306.81,673.66 U3.6
I2C2_SDA: J13.20 R30.1 U3.5 | length 800.2
  Top Layer w10: J13.20@1099.99,49.84 1099.99,94.99 1118.5,113.5 1118.5,584.5 1146.5,612.5 1194.5,612.5 1205,623 1205,697 1214.84,706.84 R30.1 1236.77,709.62 U3.5
  other v1: 1126,591
NetC8_2: C8.2 U1.9 | length 46.5
  Top Layer w10: U1.9 1734.52,602.52 1750,618 C8.2
NetC9_1: C9.1 D2.A L1.2 R8.2 R9.2 U1.7 U1.14 | length 889.2
  Top Layer w10: 1588.14,534.69 U1.14 ; U1.7 1824.5,534.69
  Top Layer w20: C9.1@1534,275 1502,307 1502,481.87 1553.5,533.37 1588.14,533.37 ; 1824.5,533.65 1844.8,533.65 1847.18,536.03 1849.33,536.03 1874.99,561.69 R9.2 1908.7,530.13 1908.7,487.4 1878.99,457.69 R8.2 1878.99,212.99
  other v1: 1489,474
NetC13_1: C13.1 C14.1 D4.K D6.K U2.10 U2.11 U2.12 | length 645.6
  Top Layer w50: 1782.79,948.04 1782.79,984.77 U2.11@1783.83,985.8
  Top Layer w80: 1782.79,948.04 1782.79,844.04 1788.83,838 1821.01,838 ; C14.1 1821.01,838 ; D6.K@2233,838 1821.01,838
NetC16_2: C16.2 U2.9 | length 89.5
  Top Layer w10: C16.2 1691,1006 1703.23,993.77 U2.9
NetL1_1: L1.1 U1.1 U1.2 U1.3 | length 63.3
  Top Layer w10: U1.3 1714.83,445.66 1736.49,424 1748,424
NetL2_1: L2.1 U2.1 U2.2 U2.3 | length 183.5
  Top Layer w20: L2.1@1771,1173 1771,1104.89 1772.7,1103.18 1807.18,1103.18 1845,1141 1870,1141
NetR7_1: R7.1 U1.13 | length 130.1
  Top Layer w10: R7.1 1556,567 1568.63,554.37 U1.13
NetR8_1: R8.1 U1.4 | length 91.4
  Top Layer w10: U1.4 1747.07,466.77 1759,454.84 R8.1
NetR9_1: R9.1 R10.2 U1.5 | length 116.3
  Top Layer w10: U1.5 1786.32,495.32 1796.84,505.84 R10.2 R9.1
NetR13_1: R13.1 R14.2 U2.5 | length 312.9
  Top Layer w10: R14.2@1606,1115 1599,1122 v1(1599,1159) 1599,1229 1610,1240 R13.1 ; v1@1695.85,1115.85 1715.92,1095.78 U2.5
  Bottom Layer w10: v1(1599,1159) 1650,1159 v1(1695,1114)
NetR18_1: R18.1 R28.2 U3.1 | length 148.4
  Top Layer w10: U3.1 1445.84,945.84 R28.2 R18.1
NetR19_1: R19.1 R22.2 U3.3 | length 289.9
  Top Layer w10: R19.1 R22.2 1289.01,1031.99 1306.81,1014.19 U3.3
NetR20_1: R20.1 R23.2 U3.2 | length 223.2
  Top Layer w10: U3.2 1332.4,1002 1386.95,1056.56 R23.2 R20.1
SKY_ADC-M1_RING: J4.19 J7.2 R39.1 | length 330.9
  Top Layer w10: J7.2 J4.19 896.26,566.26 927,597 R39.1@927,635
SKY_CTS: J4.12 J7.9 J10.35 R37.1 R37.2 | length 2513.8
  Top Layer w8: J7.9 J4.12 345.08,548.08 356,559 R37.1 R37.2
  Top Layer w10: R37.2@417,720 v1(417,879)
  Bottom Layer w10: v1(417,879) 427,889 968,889 1483,1404 1483,1432.85 J10.35@1900.03,1849.89
SKY_DIN: J4.3 J6.3 J13.13 R33.1 R33.2 | length 1732.4
  Top Layer w10: J13.13@800.03,-50.11 856.5,6.35 856.5,300.97 ; J4.3 817.52,1377.48 921.66,1273.34 R33.1 R33.2 ; 856.53,301 856.53,691.53 918.81,753.81 R33.2@918.81,1186.15
  Bottom Layer w12: J4.3 J6.3
SKY_DIO2: J4.18 J7.3 R15.1 | length 320.4
  Top Layer w10: J7.3 J4.18 817.52,629.52 R15.1
SKY_DIO3: J4.17 J7.4 R16.1 | length 465.8
  Top Layer w10: J7.4 J4.17 738.78,633.78 760.5,655.5 760.5,747 754,753.5 R16.1
SKY_DOUT: J4.2 J6.2 J13.11 R31.1 R31.2 | length 1821.4
  Top Layer w10: J13.11@700.03,-50.11 754,3.85 754,239.37 779,264.37 779,740 882,843 882,1103.05 v1@892.95,1114
  Top Layer w12: J4.2 896.26,1341.74 974.83,1263.17 R31.1 R31.2 974.83,1150.17 v1(975,1150)
  Bottom Layer w12: v1(888,1114) 924,1150 v1(975,1150) ; J4.2 J6.2
SKY_NRESET_RAW: J4.5 J6.5 Q2.3 | length 390.5
  Top Layer w12: J4.5 660.04,1369.06 712.55,1316.55 753.45,1316.55 761,1309 Q2.3
  Bottom Layer w12: J4.5 J6.5
SKY_ONOFF: J4.20 J7.1 Q1.3 | length 354.3
  Top Layer w10: J7.1 J4.20 1060,598.7 Q1.3
SKY_ONSLEEP: J4.13 J7.8 | length 196.9
  Top Layer w10: J7.8 J4.13
SKY_RTS: J4.16 J7.5 J10.33 R5.2 R35.1 R35.2 | length 2129.1
  Top Layer w10: J7.5 J4.16 660.04,664.04 676,680 R5.2 676,742 689,755 R35.1 ; R35.1@687,771 687,860 v1(750,923)
  Bottom Layer w10: v1(750,923) 960,923 1465,1428 1465,1466 1800.03,1801.03 J10.33@1800.03,1849.89
SKY_USB_N: J4.8 J5.2 | length 2858.7
  Top Layer w8: J4.8 455.69,1411.71 455.69,1463.9 493.79,1502 1147.79,1502 1279.79,1634 2665.21,1634 2695,1604.21 2695,1369.79 2651.81,1326.59 J5.2@2508,1326.59
SKY_USB_P: J4.7 J5.3 | length 2856.9
  Top Layer w8: J4.7 470.69,1411.71 470.69,1457.69 500,1487 1154,1487 1286,1619 2659,1619 2680,1598 2680,1591 2680,1585 cw(c2672,1585) 2672,1577 2669,1577 ccw(c2669,1569) 2661,1569 ccw(c2669,1569) 2669,1561 2672,1561 cw(c2672,1553) 2680,1553 cw(c2672,1553) 2672,1545 2669,1545 ccw(c2669,1537) 2661,1537 ccw(c2669,1537) 2669,1529 2672,1529 cw(c2672,1521) 2680,1521 cw(c2672,1521) 2672,1513 2669,1513 ccw(c2669,1505) 2661,1505 ccw(c2669,1505) 2669,1497 2672,1497 cw(c2672,1489) 2680,1489 2680,1376 2645.59,1341.59 J5.3@2508,1341.59
SKY_VUSB: J6.6
SYS_RESETN: C21.1 J13.10 SW1.2 | length 1050.1
  Top Layer w8: C21.1@599.99,170.84 C21.1@599.99,172.84
  Top Layer w10: SW1.2@-210,50 -210,88 -136,162 106,162 166,102 547.92,102 J13.10@600.03,49.89
  Top Layer w30: J13.10@600.03,49.89 604.99,54.84 C21.1@604.99,170.84
UART1_RXD: J13.24 R15.2 | length 1153.3
  Top Layer w10: R15.2 823,731 845,753 v1(847,753) ; v1(1261,554) 1261,89 J13.24
  Bottom Layer w10: v1(847,753) 1174,753 1261,666 v1(1261,554)
UART1_TXD: J13.26 R16.2 | length 1260.7
  Top Layer w10: R16.2 784,829 v1(803,810) ; v1(1303,583) 1318.5,567.5 1318.5,235.5 1400,154 J13.26
  Bottom Layer w10: v1(803,810) 824,789 1161,789 1301,649 v1@1301,583
UART5_RXD: J10.38 J15.1 | length 1208.2
  Bottom Layer w8: J10.38@2000.03,1944.89 2000.03,1949.89 2054,1895.92 2054,1640.22 J15.1@2670,1024.22
UART5_TXD: J10.37 J15.2 | length 1181.9
  Bottom Layer w8: J10.37@2000.03,1849.89 2032,1817.92 2032,1618 2581,1069 2581,1034.48 J15.2@2670,945.48
VCC_3V3: C17.1 J4.14 J7.7 J13.3 J13.4 J15.3 J16.3 R1.2 R2.2 R6.2 R11.2 R12.2 R18.2 R19.2 R20.2 R24.2 R29.2 R30.2 U3.8 | length 666.7
  Top Layer w10: R18.2 1554.84,900.16 v1(1555,900)
  Top Layer w15: R2.2 655,1028.84 R6.2@656.99,1030.84 ; R6.2 654.99,1072.99 v1(659,1077) ; R1.2@1092.59,867.41 R19.2 ; v1(1141,641) 1164,641 1175.99,652.99 R30.2 ; v1(1355,394) R24.2 ; U3.8 1361.77,705.84 1412.99,705.84 v1@1412.99,663.84 ; R20.2 1519,1144.4 v1(1519,1147) ; R12.2 v1@1834,1512 ; v1(1851,902) 1851,907.85 R11.2
  Top Layer w20: v1@1412.99,672.84 C17.1@1412.99,705.84
  Top Layer w60: J13.4@299.99,49.84 J13.4@300.99,50.84
  other v1: 1413.99,662.84 1091,934 1835,1511
VCC_4V0: C1.1 C2.1 C3.1 C15.1 J4.1 J6.1 L2.2 R13.2 U2.7 U2.14 | length 1071.1
  Top Layer w10: 1620.77,1026.69 1630.08,1036 1689,1036 1695,1042 U2.7@1706,1042
  Top Layer w12: U2.14 1851.3,1042 1853.97,1044.67
  Top Layer w18: 1560,1334 1560,1026.69 1620.77,1026.69
  Top Layer w20: 1855.33,1043.32 v1@1864.79,1052.78
  Bottom Layer w10: v1(1548,1033) 1716.85,1033 1744.51,1005.34 1828.34,1005.34 v1(1878,1055)
  Bottom Layer w50: J4.1 J6.1
VCC_5V0_IN: D2.K D6.A D7.K J13.5 J13.6 | length 2633.7
  Top Layer w80: D2.K@1969.31,352.31 2011.23,310.39 2096,310.39 2096,217 ; 2232,564 D6.A
  Bottom Layer w80: J13.5@399.99,-50.16 399.99,156.99 441.5,198.5 586.3,198.5 598.8,186 2054,186 2236,368 v1@2236,548
  other v1: 2100,194 2070,217 2090,249 2227,544 2255,568 2206,573
VCC_5V0_SYS: J13.7 J13.8 | length 100
  Top Layer w50: J13.7@499.99,-50.16 J13.8@499.99,49.84
VCC_12V: C10.1 C11.1 D3.K D4.A D7.A J8.1 R7.2 U1.10 U1.11 U1.12 | length 1074
  Top Layer w12: R7.2 1545,625 1587.09,582.91 U1.12
  Top Layer w60: C11.1@1683.99,676.99 1707,700 ; 1689.99,597.53 C11.1@1689.99,682.99
  Top Layer w80: 2217,430 2227,420 J8.1@2357,420
  Top Layer w100: 1707,700 1707,705.72 1720.28,719 1922,719 2211,430 2217,430
  other v1: 1903,670
VCC_SKY_VUSB: C5.1 C6.1 C7.1 C18.1 J4.6 J5.1 | length 2208.5
  Top Layer w30: C18.1@668,1262 v1@668,1284
  Top Layer w40: v1(1430,1460) 2036.52,1460 2227.52,1269 2562,1269 2569,1276
  Bottom Layer w30: J4.6 682.14,1279 1249,1279 v1(1430,1460)
  other v1: 668,1294
pads on no net: Fiducial1.Fiducial Fiducial2.Fiducial Fiducial3.Fiducial Fiducial4.Fiducial Fiducial5.Fiducial Fiducial6.Fiducial J5.0 J5.4 J6.7 J6.8 J8.2 J10.3 J10.4 J10.5 J10.6 J10.7 J10.8 J10.9 J10.10 J10.11 J10.12 J10.13 J10.14 J10.15 J10.16 J10.18 J10.19 J10.20 J10.21 J10.22 J10.23 J10.24 J10.25 J10.27 J10.28 J10.29 J10.30 J10.31 J10.32 J10.34 J10.36 J10.39 J10.40 J10.41 J10.42 J10.43 J10.44 J10.45 J10.46 J13.9 J13.14 J13.16 J13.21 J13.22 J13.28 J13.29 J13.30 J13.31 J13.32 J13.33 J13.34 J13.35 J13.36 J13.37 J13.38 J13.39 J13.40 J13.41 J13.42

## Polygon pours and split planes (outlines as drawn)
VCC_12V on Top Layer "T-12v0" (solid, remove dead copper, pour order 13): 2373,418 2373,512.24 2211.94,513.96 2114.32,621 2056,621 2056,508 2146,418 2370.14,417.83
NetL1_1 on Top Layer "T-L1_1" (solid, remove dead copper, pour order 16): 1675,483 1649,483 1625,459 1604,438 1604,413 1788,413 1791,416 1724,483 1697,483
NetL2_1 on Top Layer "T-L2_1" (solid, remove dead copper, pour order 12): 1763,1093 1763,1166 1765,1168 1985,1168 1985,1162.36 1784.46,1093
GND on Top Layer "T-GND" (solid, remove dead copper, pour order 20): 2373.31,-60.16 2452.99,-40.16 2490.99,-26.16 2527.99,-9.16 2554.83,6.07 2574.23,19 2595.99,35.84 2625.99,60.84 2654.99,89.84 2690.99,140.84 2706.49,169.34 2718.99,192.84 2730.99,218.84 2740.49,247.34 2747.99,275.84 2753.99,303.84 2753.99,1568.84 2753.99,1592.84 2744.99,1637.84 2734.99,1668.84 2721.99,1700.84 2692.99,1755.84 2648.99,1814.84 2592.99,1866.84 2556.99,1891.84 2522.99,1911.84 2478.99,1931.84 2418.61,1949.45 2379.99,1956.84 2335.51,1960.84 -336.01,1960.84 -371.01,1953.84 -402.01,1942.84 -432.01,1925.84 -458.01,1904.84 -476.51,1881.34 -492.01,1856.84 -505.01,1816.84 -509.01,1776.7 -509.01,102.85 -500.01,65.84 -485.03,30.83 -465.33,5.52 -440.44,-19.37 -412.01,-37.16 -381.01,-51.16 -350.01,-58.16 -314.01,-60.16
NetC9_1 on Top Layer "T-C9" (solid, remove dead copper, pour order 14): 1579,300 1633.16,245.84 1761.75,245.84 1916.17,245.83 1943,219 1943,165 1623.82,165 1576.99,211.84 1518.99,269.84 1518.99,300
VCC_4V0 on Top Layer "T-4v0" (solid, remove dead copper, pour order 11): 1973,1405 1955,1423 977,1423 951,1397 951,1390 951,1372 1006,1317 1769,1317 1802,1350
GND on Bottom Layer "B-GND" (solid, remove dead copper, pour order 17): 2373.31,-60.16 2452.99,-40.16 2490.99,-26.16 2527.99,-9.16 2554.83,6.07 2574.23,19 2595.99,35.84 2625.99,60.84 2654.99,89.84 2690.99,140.84 2706.49,169.34 2718.99,192.84 2730.99,218.84 2740.49,247.34 2747.99,275.84 2753.99,303.84 2753.99,1568.84 2753.99,1592.84 2744.99,1637.84 2734.99,1668.84 2721.99,1700.84 2692.99,1755.84 2648.99,1814.84 2592.99,1866.84 2556.99,1891.84 2522.99,1911.84 2478.99,1931.84 2418.61,1949.45 2379.99,1956.84 2335.51,1960.84 -336.01,1960.84 -371.01,1953.84 -402.01,1942.84 -432.01,1925.84 -458.01,1904.84 -476.51,1881.34 -492.01,1856.84 -505.01,1816.84 -509.01,1776.7 -509.01,102.85 -500.01,65.84 -485.03,30.83 -465.33,5.52 -440.44,-19.37 -412.01,-37.16 -381.01,-51.16 -350.01,-58.16 -314.01,-60.16
GND on Internal Plane 1 (split plane): 2730.88,1730.6 2730.79,1730.73 2730.77,1730.77
GND on Internal Plane 1 (split plane): 299 vertices, not listed, extent -529.94,-79.94 2779.94,1979.94
VCC_3V3 on Internal Plane 2 (split plane): 2730.88,1730.6 2730.79,1730.73 2730.77,1730.77
VCC_3V3 on Internal Plane 2 (split plane): 299 vertices, not listed, extent -529.94,-79.94 2779.94,1979.94

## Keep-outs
Keep-Out Layer:
  lines w10: 2769.9,1754.12 2788.56,1711.87 ; 2772.58,1747.87 2750.11,1788.22 2724.01,1826.32 2694.5,1861.85 2661.85,1894.5 2626.32,1924.01 2588.22,1950.11 2547.87,1972.58 2505.62,1991.24 2461.83,2005.91 2416.87,2016.49 2371.13,2022.87 2325,2025 -325,2025 -357.63,2022.86 -389.7,2016.48 -420.67,2005.97 -450,1991.51 -477.19,1973.34 -501.78,1951.78 -523.34,1927.19 -550.67,1886.29 -566.48,1839.71 -572.86,1807.63 -573.59,1796.44 -573.59,1425 200,1425 200,703.84 -575,703.84 -575,445 ; 2791.24,1705.62 2805.91,1661.83 2816.49,1616.87 2822.87,1571.13 2825,1525 2825,375 2822.87,328.87 2816.49,283.13 2805.91,238.17 2791.24,194.38 2772.58,152.13 2750.11,111.78 2724.01,73.68 2694.5,38.15 2661.85,5.5 2626.32,-24.01 2588.22,-50.11 2547.87,-72.58 2505.62,-91.24 2461.83,-105.91 2416.87,-116.49 2371.13,-122.87 2325,-125 -325,-125 -358.32,-122.77 -391.05,-116.12 -422.6,-105.16 -452.41,-90.1 -479.95,-71.19 -504.72,-48.79 -526.28,-23.28 -544.25,4.87 -558.3,35.17 -568.19,67.07 -573.75,100 -574.96,117.11 -575,165 -575,328.93 -575,445 ; -575,445 -575,445

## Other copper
Top Layer:
  rectangle net VCC_12V: 1674.99,567.84 1716.99,597.53
  rectangle net NetC13_1: 1763.99,993.77 1803.52,1009.84
  pour cut-out: 1603,357 1520,357 1516,353 1583,286 1601,286
  pour cut-out: 2002.37,148.83 2106.28,148.83 2134.95,177.5 2133.57,179.98
  pour cut-out: 1746.8,1237.98 1746.8,1305.8 1758,1317 1777,1317 1797,1337 1994.23,1337 2001.2,1330.02 2001.2,1237.98
  pour cut-out: 742.1,1232.43 692.57,1232.43 692,1233 694,1235 694,1248.25
  pour cut-out: 2288.34,777 2288.34,681.94 2275,682 2277,774 2288.34,770.06
  pour cut-out: 996,88 1064,88 1128,152 1108.5,171.5 1108.5,280.81 1104.19,280.81 1090,295 1088,293 1031,293 1031,254 1011,234
  pour cut-out: 1496.17,278 1453,278 1453,683 1458,688 1469,688 1489.28,667.72 1489.28,651.81

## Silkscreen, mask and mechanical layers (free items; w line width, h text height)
Top Overlay:
  drawing of 3868 lines, arcs and shapes, not listed
  text "2" at 134,1927 h40
  text "P8" at 115,1855 h45 r90
  text "1" at 139,1830 h40
  text "PCB: 20057 REVB" at 1987,1572 h30
  text "12V" at 2319,716 h100
  text "RESET" at -223.99,102.85 h60
  text "2" at 126.03,25.89 h40
  text "P9" at 114.03,-38.11 h45 r90
  text "1" at 139.36,-77.11 h40
Bottom Overlay:
  text "2" at 105,1943 h40
  text "P8" at 115,1855 h45 r90
  text "1" at 121,1834 h40
  text "2" at 108,49 h40
  text "P9" at 114.03,-37.11 h45 r90
  text "1" at 123,-76 h40
Mechanical 1:
  lines w10: 104.99,-125.16 104.99,725 ; 104.99,-125 2325,-125 2371.13,-122.87 2416.87,-116.49 2461.83,-105.91 2505.62,-91.24 2547.87,-72.58 2588.22,-50.11 2626.32,-24.01 2661.85,5.5 2694.5,38.15 2724.01,73.68 2750.11,111.78 2772.58,152.13 2791.24,194.38 2805.91,238.17 2816.49,283.13 2822.87,328.87 2825,375 2825,1525 2822.87,1571.13 2816.49,1616.87 2805.91,1661.83 2791.24,1705.62 ; 104.99,2025 2325,2025 2371.13,2022.87 2416.87,2016.49 2461.83,2005.91 2505.62,1991.24 2547.87,1972.58 2588.22,1950.11 2626.32,1924.01 2661.85,1894.5 2694.5,1861.85 2724.01,1826.32 2750.11,1788.22 2772.58,1747.87 ; 105.39,725 200,725 200,1425 105.99,1425 105.99,2023.8 ; 2769.9,1754.12 2788.56,1711.87
Mechanical 15:
  lines w10: -575,1425 -575,725 -575,445 ; -574.59,1425 -574.59,1796.44 ; -573.59,1796.44 -572.86,1807.63 -566.48,1839.71 -550.67,1886.29 -523.34,1927.19 -501.78,1951.78 -477.19,1973.34 -450,1991.51 -420.67,2005.97 -389.7,2016.48 -357.63,2022.86 -325,2025 2325,2025 2371.13,2022.87 2416.87,2016.49 2461.83,2005.91 2505.62,1991.24 2547.87,1972.58 2588.22,1950.11 2626.32,1924.01 2661.85,1894.5 2694.5,1861.85 2724.01,1826.32 2750.11,1788.22 2772.58,1747.87 ; -523.34,-27.42 -501.78,-52 -477.19,-73.56 -450,-91.73 -420.67,-106.19 -389.7,-116.71 -357.63,-123.09 -325,-125.22 ; 2769.9,1754.12 2788.56,1711.87 ; 2791.24,1705.62 2805.91,1661.83 2816.49,1616.87 2822.87,1571.13 2825,1525 2825,375 2822.87,328.87 2816.49,283.13 2805.91,238.17 2791.24,194.38 2772.58,152.13 2750.11,111.78 2724.01,73.68 2694.5,38.15 2661.85,5.5 2626.32,-24.01 2588.22,-50.11 2547.87,-72.58 2505.62,-91.24 2461.83,-105.91 2416.87,-116.49 2371.13,-122.87 2325,-125 -325,-125 -358.32,-122.77 -391.05,-116.12 -422.6,-105.16 -452.41,-90.1 -479.95,-71.19 -504.72,-48.79 -526.28,-23.28 -544.25,4.87 -558.3,35.17 -568.19,67.07 -573.75,100 -574.96,117.11 -575,165 -575,328.93 -575,445 ; -575,445 -575,445
Drill Drawing:
  drawing of 1953 lines, arcs and shapes, not listed
  text "FIDUCIAL" at 3366.03,11586.89 h45
  text "FIDUCIAL" at -1515.97,11583.89 h45
  text "Cutout" at -1339.97,11415.89 h45
  text "Cutout" at 3437.03,11349.89 h45
  text "Cutout" at -260.97,10844.89 h45
  text "Copy Artwork" at 577.03,10677.89 h45
  text "Cutout" at 3437.03,9961.89 h45
  text "Cutout" at -1339.97,9795.89 h45
  text "VSCORE" at -1349.97,9605.89 h45
  text "VSCORE" at -1349.97,9325.89 h45
  text "Cutout" at -1343.97,9101.89 h45
  text "Cutout" at 3456.03,8938.89 h45
  text "Copy Artwork" at 577.03,8339.89 h45
  text "Cutout" at -319.97,8331.89 h45
  text "Cutout" at 3456.03,7550.89 h45
  text "Cutout" at -1343.97,7481.89 h45
  text "VSCORE" at -1349.97,7165.89 h45
  text "VSCORE" at -1349.97,6885.89 h45
  text "Cutout" at -1339.97,6649.89 h45
  text "Cutout" at 3430.03,6476.89 h45
  text "Cutout" at -268.97,5921.89 h45
  text "Copy Artwork" at 577.03,5904.89 h45
  text "Layer" at 7027.08,5425.84 h60
  text "Name" at 7436.99,5425.84 h60
  text "Material" at 8476.7,5425.84 h60
  text "Thickness" at 9336.46,5425.84 h60
  text "Constant" at 9986.3,5425.84 h60
  text "Board Layer Stack" at 10556.16,5425.84 h60
  text "1" at 7027.08,5305.84 h60
  text "Top Overlay" at 7436.99,5305.84 h60
  text "2" at 7027.08,5185.84 h60
  text "Top Solder" at 7436.99,5185.84 h60
  text "Solder Resist" at 8476.7,5185.84 h60
  text "0.40mil" at 9336.46,5185.84 h60
  text "3.5" at 9986.3,5185.84 h60
  text "Cutout" at 3430.03,5088.89 h45
  text "3" at 7027.08,5065.84 h60
  text "Top Layer" at 7436.99,5065.84 h60
  text "Copper" at 8476.7,5065.84 h60
  text "1.37mil" at 9336.46,5065.84 h60
  text "Cutout" at -1339.97,5029.89 h45
  text "4" at 7027.08,4945.84 h60
  text "Dielectric 1" at 7436.99,4945.84 h60
  text "FR-4" at 8476.7,4945.84 h60
  text "6.70mil" at 9336.46,4945.84 h60
  text "4.6" at 9986.3,4945.84 h60
  text "5" at 7027.08,4825.84 h60
  text "Internal Plane 1" at 7436.99,4825.84 h60
  text "Copper" at 8476.7,4825.84 h60
  text "1.37mil" at 9336.46,4825.84 h60
  text "VSCORE" at -1349.97,4725.89 h45
  text "6" at 7027.08,4705.84 h60
  text "Dielectric 3" at 7436.99,4705.84 h60
  text "47.20mil" at 9336.46,4705.84 h60
  text "4.6" at 9986.3,4705.84 h60
  text "7" at 7027.08,4585.84 h60
  text "Internal Plane 2" at 7436.99,4585.84 h60
  text "Copper" at 8476.7,4585.84 h60
  text "1.37mil" at 9336.46,4585.84 h60
  text "8" at 7027.08,4465.84 h60
  text "Dielectric 2" at 7436.99,4465.84 h60
  text "6.70mil" at 9336.46,4465.84 h60
  text "4.6" at 9986.3,4465.84 h60
  text "VSCORE" at -1349.97,4445.89 h45
  text "9" at 7027.08,4345.84 h60
  text "Bottom Layer" at 7436.99,4345.84 h60
  text "Copper" at 8476.7,4345.84 h60
  text "1.37mil" at 9336.46,4345.84 h60
  text "10" at 7027.08,4225.84 h60
  text "Bottom Solder" at 7436.99,4225.84 h60
  text "Solder Resist" at 8476.7,4225.84 h60
  text "0.40mil" at 9336.46,4225.84 h60
  text "3.5" at 9986.3,4225.84 h60
  text "Cutout" at -1349.97,4162.89 h45
  text "11" at 7027.08,4105.84 h60
  text "Bottom Overlay" at 7436.99,4105.84 h60
  text "Cutout" at 3444.03,4004.89 h45
  text "Symbol" at 7066.3,3774.84 h72
  text "Hit Count" at 7572.17,3774.84 h72
  text "Finished Hole Size" at 8269.99,3774.84 h72
  text "Plated" at 9615.59,3774.84 h72
  text "Hole Type" at 10121.47,3774.84 h72
  text "1" at 7572.17,3624.84 h60
  text "39.37mil (1.000mm)" at 8269.99,3624.84 h60
  text "PTH" at 9615.59,3624.84 h60
  text "Slot" at 10121.47,3624.84 h60
  text "Copy Artwork" at 577.03,3566.89 h45
  text "2" at 7572.17,3474.84 h60
  text "35.43mil (0.900mm)" at 8269.99,3474.84 h60
  text "NPTH" at 9615.59,3474.84 h60
  text "Round" at 10121.47,3474.84 h60
  text "Cutout" at -302.97,3459.89 h45
  text "2" at 7572.17,3324.84 h60
  text "39.37mil (1.000mm)" at 8269.99,3324.84 h60
  text "PTH" at 9615.59,3324.84 h60
  text "Slot" at 10121.47,3324.84 h60
  text "4" at 7572.17,3174.84 h60
  text "120.00mil (3.048mm)" at 8269.99,3174.84 h60
  text "PTH" at 9615.59,3174.84 h60
  text "Round" at 10121.47,3174.84 h60
  text "8" at 7572.17,3024.84 h60
  text "28.00mil (0.711mm)" at 8269.99,3024.84 h60
  text "PTH" at 9615.59,3024.84 h60
  text "Round" at 10121.47,3024.84 h60
  text "8" at 7572.17,2874.84 h60
  text "65.00mil (1.651mm)" at 8269.99,2874.84 h60
  text "PTH" at 9615.59,2874.84 h60
  text "Round" at 10121.47,2874.84 h60
  text "40" at 7572.17,2724.84 h60
  text "31.50mil (0.800mm)" at 8269.99,2724.84 h60
  text "PTH" at 9615.59,2724.84 h60
  text "Round" at 10121.47,2724.84 h60
  text "Cutout" at 3444.03,2616.89 h45
  text "92" at 7572.17,2574.84 h60
  text "40.00mil (1.016mm)" at 8269.99,2574.84 h60
  text "PTH" at 9615.59,2574.84 h60
  text "Round" at 10121.47,2574.84 h60
  text "Cutout" at -1349.97,2542.89 h45
  text "184" at 7572.17,2424.84 h60
  text "15.00mil (0.381mm)" at 8269.99,2424.84 h60
  text "PTH" at 9615.59,2424.84 h60
  text "Round" at 10121.47,2424.84 h60
  text "VSCORE" at -1349.97,2285.89 h45
  text "341 Total" at 7572.17,2274.84 h60
  text "VSCORE" at -1349.97,2005.89 h45
  text "NOTES:" at 7113.99,1762.84 h56.25
  text "1. BOARD IS A 5x1 ARRAY. SEE PANEL ARTWORK LAYER FOR PANEL DETAIL." at 7113.99,1656.84 h56.25
  text "Cutout" at 3448.03,1613.89 h45
  text "2. BOARD TO BE SCORED AT DESIGNATED LINES. SCORING TO BE 30 DEG." at 7113.99,1542.7 h56.25
  text "3. BOARD TO USE Tg 170C OR GREATER" at 7113.99,1433.84 h56.25
  text "4. BOARD THICKNESS TOLERANCE +/- 10%" at 7113.99,1314.41 h56.25
  text "5) BOARD TO USE GREEN SOLDER MASK" at 7113.99,1200.27 h56.25
  text "6) BOARD TO USE WHITE SILK SCREEN" at 7113.99,1086.13 h56.25
  text "Cutout" at -279.97,1073.89 h45
  text "7) MIN HOLE WALL THICKNESS 1 mil" at 7113.99,971.99 h56.25
  text "8) BOARD TO USE ENIG SURFACE FINISH" at 7113.99,857.84 h56.25
  text "9) COPPER LAYERS TO BE 1OZ COPPER" at 7109.99,748.84 h56.25
  text "Cutout" at 3448.03,225.89 h45
  text "FIDUCIAL" at -1515.97,52.89 h45
  text "VSCORE" at 2749.03,-303.11 h45
  text "VSCORE" at -649.97,-310.11 h45

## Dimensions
2825.03,-326.11 to -574.97,-332.11 on Drill Drawing
3681,2030 to 3687,-130 on Drill Drawing
-959.97,11790.89 to -579.97,11790.89 on Drill Drawing
2830.03,11789 to 3180.03,11790.89 on Drill Drawing
3180.03,-130.11 to -959.97,-130.11 on Drill Drawing
-809.97,99.89 to -959.97,-130.11 on Drill Drawing
-878.97,69.89 to -959.97,-130.11 on Drill Drawing
-878.97,11590.89 to -959.97,11790.89 on Drill Drawing
-809.97,11560.89 to -959.97,11790.89 on Drill Drawing
3049.03,11590.89 to 3145.03,11790.89 on Drill Drawing
2980.03,11560.89 to 3180.03,11790.89 on Drill Drawing
3180,-130.11 to 3180,11790.89 on Drill Drawing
